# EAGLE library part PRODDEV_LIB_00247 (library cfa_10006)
CFAG19264D
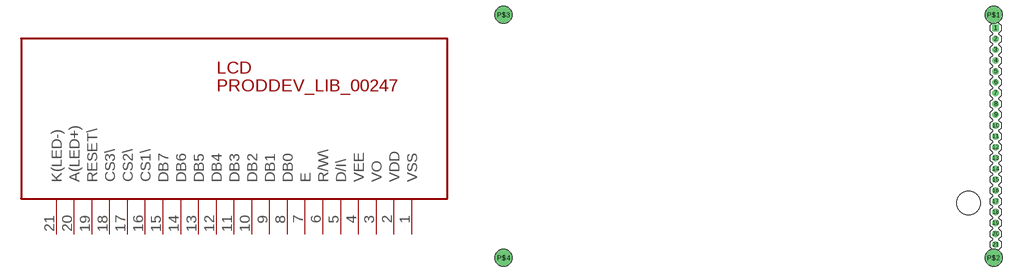
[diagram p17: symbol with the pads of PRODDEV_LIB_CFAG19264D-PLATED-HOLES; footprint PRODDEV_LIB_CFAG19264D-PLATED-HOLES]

Designator prefix LCD

## PRODDEV_LIB_00247  [PRODDEV_LIB_CFAG19264D-PLATED-HOLES]
1  VSS  pwr
2  VDD  pwr
3  VO  pas
4  VEE  pas
5  D/I\  in
6  R/W\  in
7  E  in
8  DB0
9  DB1
10  DB2
11  DB3
12  DB4
13  DB5
14  DB6
15  DB7
16  CS1\  in
17  CS2\  in
18  CS3\  in
19  RESET\  in
20  A(LED+)  in
21  K(LED-)  in

## Footprint PRODDEV_LIB_CFAG19264D-PLATED-HOLES (pad centres in mm)
BFAG19264D
drill 1 square: 1 0,0
drill 1 round: 2 0,-2.54; 3 0,-5.08; 4 0,-7.62; 5 0,-10.16; 6 0,-12.7; 7 0,-15.24; 8 0,-17.78; 9 0,-20.32; 10 0,-22.86; 11 0,-25.4; 12 0,-27.94; 13 0,-30.48; 14 0,-33.02; 15 0,-35.56; 16 0,-38.1; 17 0,-40.64; 18 0,-43.18; 19 0,-45.72; 20 0,-48.26; 21 0,-50.8
drill 2.7 round: P$1 -0.5,3.1; P$2 -0.5,-53.9; P$3 -115.5,3.1; P$4 -115.5,-53.9
hole 5.5 at -6.4,-41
